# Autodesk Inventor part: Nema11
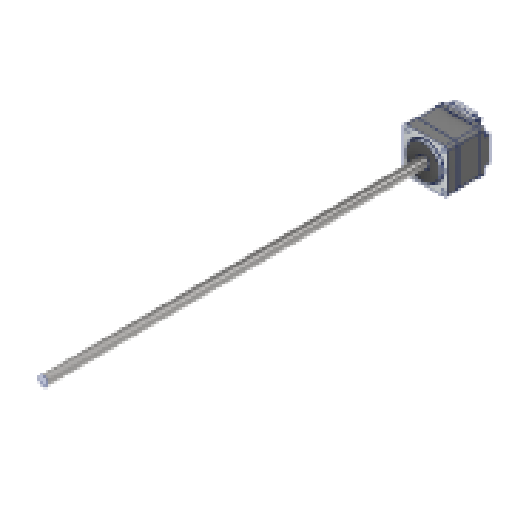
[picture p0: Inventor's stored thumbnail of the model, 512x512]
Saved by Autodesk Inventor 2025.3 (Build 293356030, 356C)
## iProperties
Created: 2019-06
Part Number: Nema11
Material: Generico
Document SubType Name: Modeling
Designer: R5800u
Density: 1 g/cm^3
Appearance: Default
Sending System: SolidWorks 2021
Last Author: Albert
Last Saved: 2021-07-29
Author: R5800u
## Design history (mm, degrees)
feature "Shaft"
sketch "Schizzo1"
  geometry: C1 r 3 at (0, 0) reference; 1 further point
  node "Linea chiusa proiettata1"
node "Piano di lavoro1"
extrude "Estrusione1" join sketch "Schizzo1" stored distance "d0" = 10; taper "d1" = 0 deg
node "Solido1"
